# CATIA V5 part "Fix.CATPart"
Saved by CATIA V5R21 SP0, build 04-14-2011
Part number: Fix
Bounding box of the stored display mesh (mm): x 0 to 0, y -46.558 to 52.129, z -41.874 to 44.267
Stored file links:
  D:\CATIA V5R21 E-RESOURCES\CATIA-V5R21\catia-v5r21-prt\c16-catia-v5r20-prt\Point Curve Joint-(16-36)\CAT_V5R21_Fix.CATPart
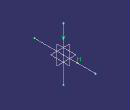
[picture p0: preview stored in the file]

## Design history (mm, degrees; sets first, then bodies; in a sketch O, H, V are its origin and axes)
Body1 (main body)
  Sketch1 on yz-plane, origin (0, 0, 0), H (0, 1, 0), V (0, 0, 1)
    line L1 (0, 44.267) -> (0, -41.8742)
    point P1 (0, 44.267)
    line L2 (-46.5584, 0) -> (52.1295, 0)
    point P3 (-46.5584, 0)
    coincidence: P1 V, P3 H
    vertical: L1 V
    horizontal: L2 H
